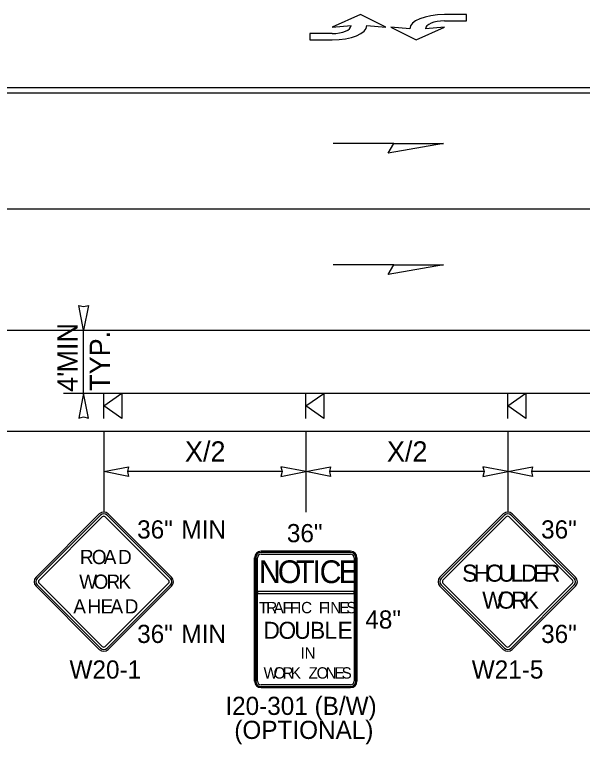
# Model space of a CAD drawing. Extents: x 99999.1 to 100096.1, y 99995 to 100010.7.
# Drawn here: x 100042.095 to 100044.344, y 100003.745 to 100006.636 of the extents above; entities that cross this region are included whole.
import ezdxf

# ---------------------------------------------------------------- set-up
doc = ezdxf.new("R2010")
doc.units = 0
for name, color, linetype in [('RD_ED_ShoulderPavedEdge', 7, 'Continuous'), ('RD_MK_LineEdgeWhite', 7, 'Continuous'), ('RD_MK_LineLane', 7, 'Continuous'), ('RD_MK_LineTwoWayLtTurn', 7, 'Continuous'), ('TR_SN_ConstructionSigns', 7, 'Continuous'), ('TR_WZ_PortableSignMountBlk-Org', 7, 'Continuous'), ('TR_WZ_PortableSignMountBlk-Wht', 7, 'Continuous'), ('TR_WZ_WorkZoneDetails', 7, 'Continuous'), ('TR_WZ_WorkZoneTextCurrent', 7, 'Continuous')]:
    doc.layers.add(name, color=color, linetype=linetype)

msp = doc.modelspace()

# ---------------------------------------------------------------- linework, layer by layer
at = {"layer": 'RD_ED_ShoulderPavedEdge'}
msp.add_line((100040.8283, 100004.9857), (100054.8933, 100004.9857), dxfattribs=at)
at = {"layer": 'RD_MK_LineEdgeWhite'}
msp.add_line((100040.8283, 100005.3857), (100054.8933, 100005.3857), dxfattribs=at)
at = {"layer": 'RD_MK_LineLane'}
msp.add_lwpolyline([(100054.8933, 100005.8657), (100040.8283, 100005.8657)], dxfattribs=at)
at = {"layer": 'RD_MK_LineTwoWayLtTurn'}
msp.add_line((100040.8283, 100006.3257), (100054.8933, 100006.3257), dxfattribs=at)
msp.add_lwpolyline([(100054.8933, 100006.3457), (100040.8283, 100006.3457)], dxfattribs=at)
at = {"layer": 'TR_SN_ConstructionSigns'}
for p, q in [((100042.4307, 100004.6583), (100042.1801, 100004.4077)), ((100042.4357, 100004.6533), (100042.1851, 100004.4028)), ((100042.1921, 100004.3958), (100042.4426, 100004.6464)), ((100042.4546, 100004.6464), (100042.7052, 100004.3958)), ((100042.7121, 100004.4028), (100042.4615, 100004.6533)), ((100042.7171, 100004.4077), (100042.4665, 100004.6583)), ((100044.0307, 100004.6583), (100043.7801, 100004.4077)), ((100044.0357, 100004.6533), (100043.7851, 100004.4028)), ((100043.7921, 100004.3958), (100044.0426, 100004.6464)), ((100044.0546, 100004.6464), (100044.3052, 100004.3958)), ((100044.3121, 100004.4028), (100044.0615, 100004.6533)), ((100044.3171, 100004.4077), (100044.0665, 100004.6583)), ((100043.0714, 100004.51), (100043.4258, 100004.51)), ((100043.4258, 100004.51), (100043.0714, 100004.51)), ((100043.4258, 100004.51), (100043.0714, 100004.51)), ((100043.4258, 100004.5058), (100043.0714, 100004.5058)), ((100043.0714, 100004.4988), (100043.4258, 100004.4988)), ((100043.0461, 100003.9953), (100043.0461, 100004.4847)), ((100043.0461, 100004.4847), (100043.0461, 100003.9953)), ((100043.0461, 100004.4847), (100043.0461, 100003.9953)), ((100043.0503, 100004.4847), (100043.0503, 100003.9953)), ((100043.0574, 100004.3504), (100043.0574, 100004.4847)), ((100043.4399, 100004.4847), (100043.4399, 100004.3504)), ((100043.4469, 100003.9953), (100043.4469, 100004.4847)), ((100043.4511, 100004.4847), (100043.4511, 100003.9953)), ((100043.4511, 100003.9953), (100043.4511, 100004.4847)), ((100043.4511, 100003.9953), (100043.4511, 100004.4847)), ((100042.1801, 100004.3719), (100042.4307, 100004.1214)), ((100042.1851, 100004.3769), (100042.4357, 100004.1263)), ((100042.4426, 100004.1333), (100042.1921, 100004.3839)), ((100042.7052, 100004.3839), (100042.4546, 100004.1333)), ((100042.4615, 100004.1263), (100042.7121, 100004.3769)), ((100042.4665, 100004.1214), (100042.7171, 100004.3719)), ((100043.7801, 100004.3719), (100044.0307, 100004.1214)), ((100043.7851, 100004.3769), (100044.0357, 100004.1263)), ((100044.0426, 100004.1333), (100043.7921, 100004.3839)), ((100044.3052, 100004.3839), (100044.0546, 100004.1333)), ((100044.0615, 100004.1263), (100044.3121, 100004.3769)), ((100044.0665, 100004.1214), (100044.3171, 100004.3719)), ((100043.0574, 100004.3504), (100043.0574, 100004.3504)), ((100043.4399, 100004.3504), (100043.0574, 100004.3504)), ((100043.0574, 100004.3504), (100043.0574, 100004.3434)), ((100043.0574, 100004.3434), (100043.0574, 100004.3504)), ((100043.0574, 100004.3434), (100043.4399, 100004.3434)), ((100043.0574, 100003.9953), (100043.0574, 100004.3434)), ((100043.4399, 100004.3434), (100043.4399, 100004.3504)), ((100043.4399, 100004.3504), (100043.4399, 100004.3434)), ((100043.4399, 100004.3434), (100043.4399, 100003.9953)), ((100043.4258, 100003.9813), (100043.0714, 100003.9813)), ((100043.0714, 100003.9742), (100043.4258, 100003.9742)), ((100043.4258, 100003.97), (100043.0714, 100003.97)), ((100043.0714, 100003.97), (100043.4258, 100003.97)), ((100043.0714, 100003.97), (100043.4258, 100003.97))]:
    msp.add_line(p, q, dxfattribs=at)
for centre, radius, start, end in [((100042.4486, 100004.6404), 0.0253, 45, 135), ((100044.0486, 100004.6404), 0.0253, 45, 135), ((100042.4486, 100004.6404), 0.0183, 45, 135), ((100042.4486, 100004.6404), 0.00844, 45, 135), ((100044.0486, 100004.6404), 0.0183, 45, 135), ((100044.0486, 100004.6404), 0.00844, 45, 135), ((100043.0714, 100004.4847), 0.0253, 90, 180), ((100043.0714, 100004.4847), 0.0253, 90, 180), ((100043.0714, 100004.4847), 0.0253, 90, 180), ((100043.0714, 100004.4847), 0.0211, 90, 180), ((100043.0714, 100004.4847), 0.0141, 90, 180), ((100043.4258, 100004.4847), 0.0253, 0, 90), ((100043.4258, 100004.4847), 0.0253, 0, 90), ((100043.4258, 100004.4847), 0.0253, 0, 90), ((100043.4258, 100004.4847), 0.0211, 0, 90), ((100043.4258, 100004.4847), 0.0141, 0, 90), ((100042.198, 100004.3898), 0.0253, 135, 225), ((100042.198, 100004.3898), 0.0183, 135, 225), ((100042.6992, 100004.3898), 0.0183, 315, 45), ((100042.6992, 100004.3898), 0.0253, 315, 45), ((100043.798, 100004.3898), 0.0253, 135, 225), ((100043.798, 100004.3898), 0.0183, 135, 225), ((100044.2992, 100004.3898), 0.0183, 315, 45), ((100044.2992, 100004.3898), 0.0253, 315, 45), ((100042.198, 100004.3898), 0.00844, 135, 225), ((100042.6992, 100004.3898), 0.00844, 315, 45), ((100043.798, 100004.3898), 0.00844, 135, 225), ((100044.2992, 100004.3898), 0.00844, 315, 45), ((100042.4486, 100004.1393), 0.0253, 225, 315), ((100042.4486, 100004.1393), 0.0183, 225, 315), ((100042.4486, 100004.1393), 0.00844, 225, 315), ((100044.0486, 100004.1393), 0.0253, 225, 315), ((100044.0486, 100004.1393), 0.0183, 225, 315), ((100044.0486, 100004.1393), 0.00844, 225, 315), ((100043.0714, 100003.9953), 0.0253, 180, 270), ((100043.0714, 100003.9953), 0.0253, 180, 270), ((100043.0714, 100003.9953), 0.0253, 180, 270), ((100043.0714, 100003.9953), 0.0211, 180, 270), ((100043.0714, 100003.9953), 0.0141, 180, 270), ((100043.4258, 100003.9953), 0.0253, 270, 0), ((100043.4258, 100003.9953), 0.0253, 270, 0), ((100043.4258, 100003.9953), 0.0211, 270, 0), ((100043.4258, 100003.9953), 0.0141, 270, 0), ((100043.4258, 100003.9953), 0.0253, 270, 0)]:
    msp.add_arc(centre, radius, start, end, dxfattribs=at)
at = {"layer": 'TR_WZ_PortableSignMountBlk-Org'}
for p, q in [((100042.4486, 100005.0358), (100042.4486, 100005.1358)), ((100044.0486, 100005.0358), (100044.0486, 100005.1358))]:
    msp.add_line(p, q, dxfattribs=at)
for points in [[(100042.4486, 100005.0857), (100042.5204, 100005.1358), (100042.5204, 100005.0358)], [(100044.0486, 100005.0857), (100044.1204, 100005.1358), (100044.1204, 100005.0358)]]:
    msp.add_lwpolyline(points, close=True, dxfattribs=at)
at = {"layer": 'TR_WZ_PortableSignMountBlk-Wht'}
msp.add_line((100043.2486, 100005.0357), (100043.2486, 100005.1357), dxfattribs=at)
msp.add_lwpolyline([(100043.2486, 100005.0856), (100043.3204, 100005.1357), (100043.3204, 100005.0357)], close=True, dxfattribs=at)
at = {"layer": 'TR_WZ_WorkZoneDetails'}
for p, q in [((100043.5976, 100006.125), (100043.3565, 100006.125)), ((100043.5976, 100005.645), (100043.3565, 100005.645)), ((100042.2886, 100005.3857), (100042.4486, 100005.3857)), ((100042.3686, 100005.1358), (100042.3686, 100005.3857)), ((100042.2886, 100005.1358), (100042.4486, 100005.1358)), ((100042.4486, 100005.1358), (100045.9101, 100005.1358)), ((100042.4486, 100004.9857), (100042.4486, 100004.6657)), ((100043.2486, 100004.986), (100043.2486, 100004.6657)), ((100044.0486, 100004.986), (100044.0486, 100004.6657)), ((100043.1549, 100004.8257), (100042.5423, 100004.8257)), ((100043.9549, 100004.8257), (100043.3423, 100004.8257)), ((100044.9549, 100004.8257), (100044.1423, 100004.8257))]:
    msp.add_line(p, q, dxfattribs=at)
for points in [[(100043.4903, 100006.5919), (100043.5653, 100006.5857), (100043.4653, 100006.6357), (100043.3528, 100006.5857), (100043.4278, 100006.5919)], [(100043.7978, 100006.6107), (100043.8853, 100006.6107), (100043.8853, 100006.6357), (100043.7978, 100006.6357)], [(100043.6603, 100006.5795), (100043.5853, 100006.5857), (100043.6853, 100006.5357), (100043.7978, 100006.5857), (100043.7228, 100006.5795)], [(100043.3528, 100006.5607), (100043.2653, 100006.5607), (100043.2653, 100006.5357), (100043.3528, 100006.5357)]]:
    msp.add_lwpolyline(points, dxfattribs=at)
for points in [[(100043.7941, 100006.125), (100043.5753, 100006.0864), (100043.5976, 100006.125)], [(100043.7941, 100005.645), (100043.5753, 100005.6064), (100043.5976, 100005.645)], [(100042.3686, 100005.3857), (100042.3493, 100005.484), (100042.3686, 100005.4795), (100042.3879, 100005.484)], [(100042.3686, 100005.1358), (100042.3493, 100005.0375), (100042.3686, 100005.0421), (100042.3879, 100005.0375)], [(100042.4486, 100004.8257), (100042.5469, 100004.845), (100042.5423, 100004.8257), (100042.5469, 100004.8065)], [(100043.2486, 100004.8257), (100043.1503, 100004.845), (100043.1549, 100004.8257), (100043.1503, 100004.8065)], [(100043.2486, 100004.8257), (100043.3469, 100004.845), (100043.3423, 100004.8257), (100043.3469, 100004.8065)], [(100044.0486, 100004.8257), (100043.9503, 100004.845), (100043.9549, 100004.8257), (100043.9503, 100004.8065)], [(100044.0486, 100004.8257), (100044.1469, 100004.845), (100044.1423, 100004.8257), (100044.1469, 100004.8065)]]:
    msp.add_lwpolyline(points, close=True, dxfattribs=at)
for centre, major_axis, ratio, start_param in [((100043.7978, 100006.5795), (-0.1375, 0), 0.40879, 4.712524), ((100043.7978, 100006.5795), (-0.075, 0), 0.41611, 4.712518), ((100043.3528, 100006.5919), (0.075, 0), 0.41611, 4.712518), ((100043.3528, 100006.5919), (0.1375, 0), 0.40879, 4.712524)]:
    msp.add_ellipse(centre, major_axis=major_axis, ratio=ratio, start_param=start_param, end_param=6.283185, dxfattribs=at)

# ---------------------------------------------------------------- texts
at = {"layer": 'TR_SN_ConstructionSigns'}
for s, p in [('36"', (100042.5807, 100004.5607)), ('MIN', (100042.7562, 100004.5607)), ('36"', (100044.1807, 100004.5607)), ('36"', (100043.1738, 100004.546)), ('48"', (100043.4844, 100004.204)), ('36"', (100042.5807, 100004.147)), ('MIN', (100042.7562, 100004.147)), ('36"', (100044.1807, 100004.147)), ('W20-1', (100042.3128, 100004.0059)), ('W21-5', (100043.9061, 100004.0059)), ('I20-301 (B/W)', (100042.93, 100003.862)), ('(OPTIONAL)', (100042.9655, 100003.7669))]:
    msp.add_text(s, height=0.072, rotation=360, dxfattribs=at).set_placement(p)
for s, height, p in [('R', 0.0562, (100042.354, 100004.4594)), ('O', 0.0562, (100042.401, 100004.4594)), ('A', 0.0562, (100042.4484, 100004.4594)), ('D', 0.0562, (100042.5049, 100004.4594)), ('N', 0.09, (100043.0629, 100004.3842)), ('O', 0.09, (100043.1379, 100004.3842)), ('T', 0.09, (100043.21, 100004.3842)), ('I', 0.09, (100043.2753, 100004.3842)), ('C', 0.09, (100043.3035, 100004.3842)), ('E', 0.09, (100043.3786, 100004.3842)), ('S', 0.0675, (100043.8679, 100004.3898)), ('H', 0.0675, (100043.914, 100004.3898)), ('O', 0.0675, (100043.9616, 100004.3898)), ('U', 0.0675, (100044.0113, 100004.3898)), ('L', 0.0675, (100044.0599, 100004.3898)), ('D', 0.0675, (100044.1012, 100004.3898)), ('E', 0.0675, (100044.1488, 100004.3898)), ('R', 0.0675, (100044.1915, 100004.3898)), ('W', 0.0562, (100042.3511, 100004.3617)), ('O', 0.0562, (100042.408, 100004.3617)), ('R', 0.0562, (100042.4595, 100004.3617)), ('K', 0.0562, (100042.5067, 100004.3617)), ('W', 0.0675, (100043.9474, 100004.283)), ('O', 0.0675, (100044.0074, 100004.283)), ('R', 0.0675, (100044.0619, 100004.283)), ('K', 0.0675, (100044.1121, 100004.283)), ('A', 0.0562, (100042.3277, 100004.264)), ('H', 0.0562, (100042.3839, 100004.264)), ('E', 0.0562, (100042.4357, 100004.264)), ('A', 0.0562, (100042.4751, 100004.264)), ('D', 0.0562, (100042.5313, 100004.264)), ('T', 0.045, (100043.0628, 100004.2646)), ('R', 0.045, (100043.092, 100004.2646)), ('A', 0.045, (100043.1213, 100004.2646)), ('F', 0.045, (100043.1564, 100004.2646)), ('F', 0.045, (100043.1856, 100004.2646)), ('I', 0.045, (100043.2149, 100004.2646)), ('C', 0.045, (100043.2302, 100004.2646)), ('F', 0.045, (100043.3004, 100004.2646)), ('I', 0.045, (100043.3296, 100004.2646)), ('N', 0.045, (100043.3458, 100004.2646)), ('E', 0.045, (100043.3809, 100004.2646)), ('S', 0.045, (100043.4093, 100004.2646)), ('D', 0.0675, (100043.0809, 100004.1634)), ('O', 0.0675, (100043.1403, 100004.1634)), ('U', 0.0675, (100043.2031, 100004.1634)), ('B', 0.0675, (100043.2652, 100004.1634)), ('L', 0.0675, (100043.3225, 100004.1634)), ('E', 0.0675, (100043.3745, 100004.1634)), ('I', 0.045, (100043.2279, 100004.0846)), ('N', 0.045, (100043.2441, 100004.0846)), ('W', 0.045, (100043.0814, 100004.0059)), ('O', 0.045, (100043.121, 100004.0059)), ('R', 0.045, (100043.1566, 100004.0059)), ('K', 0.045, (100043.1894, 100004.0059)), ('Z', 0.045, (100043.2596, 100004.0059)), ('O', 0.045, (100043.2916, 100004.0059)), ('N', 0.045, (100043.3271, 100004.0059)), ('E', 0.045, (100043.3622, 100004.0059)), ('S', 0.045, (100043.3906, 100004.0059))]:
    msp.add_text(s, height=height, dxfattribs=at).set_placement(p)
at = {"layer": 'TR_WZ_WorkZoneTextCurrent'}
for s, rotation, p in [('MIN', 90, (100042.3446, 100005.2182)), ('TYP.', 90, (100042.4726, 100005.1454)), ("4'", 90, (100042.3446, 100005.1417)), ('X/2', 360, (100042.7701, 100004.8657)), ('X/2', 360, (100043.5701, 100004.8657))]:
    msp.add_text(s, height=0.08, rotation=rotation, dxfattribs=at).set_placement(p)

doc.saveas('drawing.dxf')
